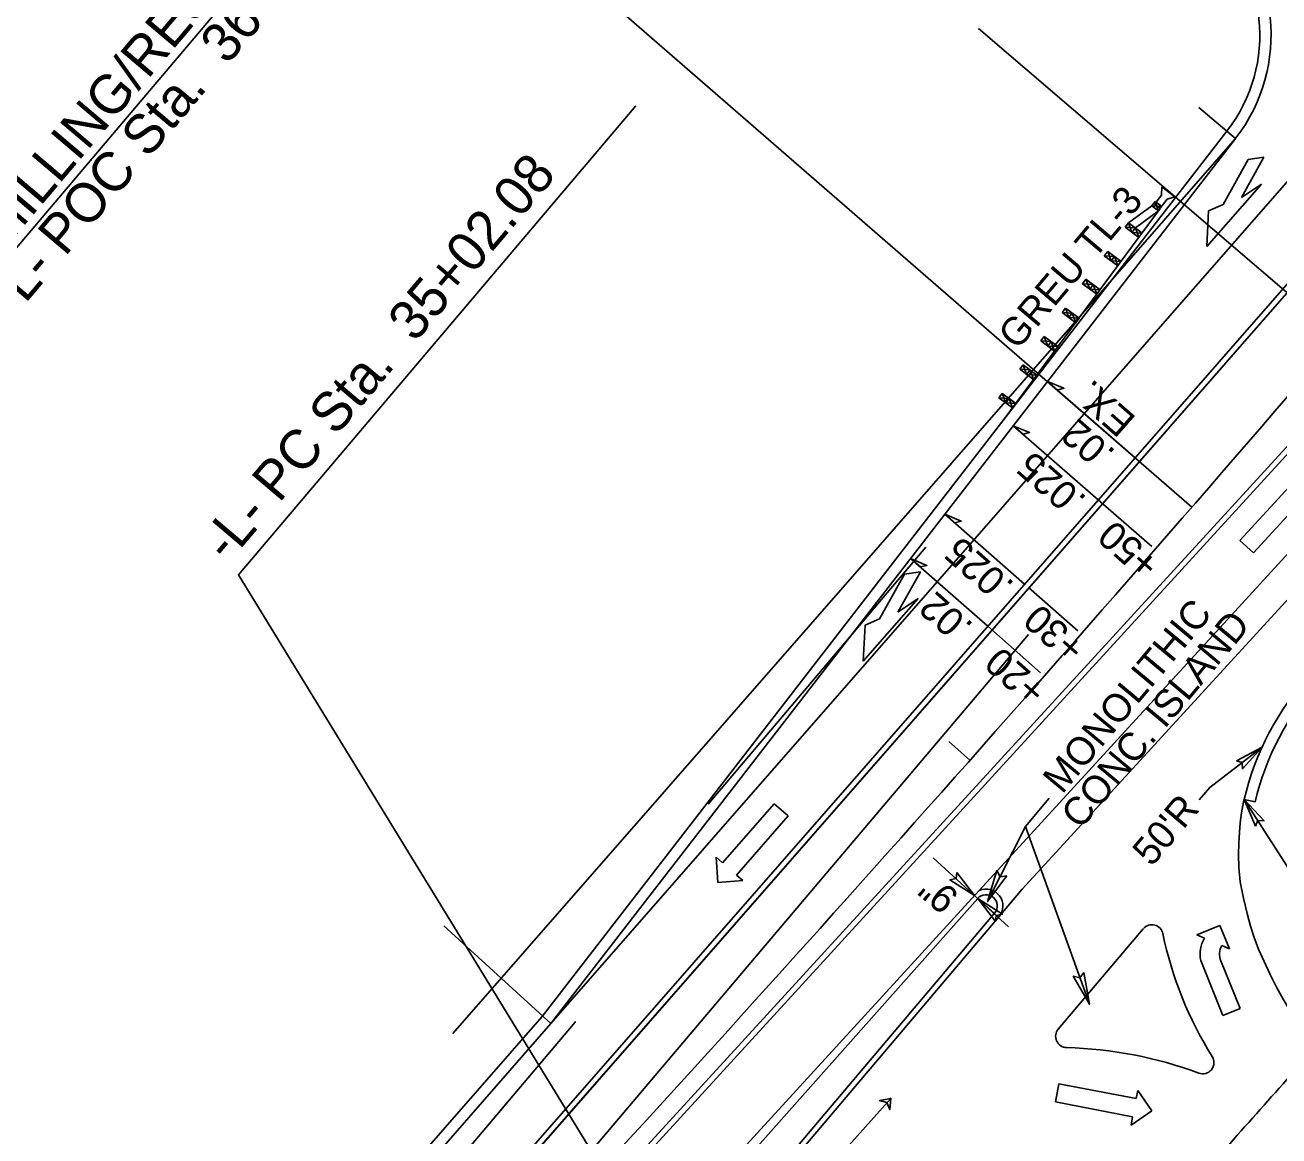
# Model space of a CAD drawing. Extents: x 1761082 to 1764358, y 421907 to 425434.
# Drawn here: x 1762805.2 to 1763028.7, y 423828.1 to 424026 of the extents above; entities that cross this region are included whole.
import ezdxf

# ---------------------------------------------------------------- set-up
doc = ezdxf.new("R2010")
doc.units = 0
for name, color, linetype in [('MARK DUAL LEFT TURN ARROWS CELL', 7, 'Continuous'), ('MARK HOOKS CENTER STRAIGHT LEFT TURN ARROW CELL', 7, 'Continuous'), ('MARK LEFT TURN ARROW CELL', 7, 'Continuous'), ('MARK STRAIGHT RIGHT ARROW CELL', 7, 'Continuous'), ('MARK UTURN ARROW CELL', 7, 'Continuous'), ('Prop Mkg 3ft Min Skp 3ft Wide White', 7, 'Continuous'), ('Prop Mkg 3ft Min Skp 9ft Wide White', 7, 'Continuous'), ('Prop Mkg Min Skp 6ft Yellow', 7, 'Continuous'), ('Prop Mkg Skp Wht', 7, 'Continuous'), ('Prop Mkg Solid White Diagonals', 7, 'Continuous'), ('Prop Mkg Solid White Edge Line', 7, 'Continuous'), ('Prop Mkg Solid White Lane Line', 7, 'Continuous'), ('Prop Mkg Solid White Multiple Diagonals V8i', 7, 'Continuous'), ('Prop Mkg Solid Yel Skip LT', 7, 'Continuous'), ('Prop Mkg Solid Yel Skip RT', 7, 'Continuous'), ('Prop Mkg Solid Yellow Diagonals', 7, 'Continuous'), ('Prop Mkg Solid Yellow Edge Line', 7, 'Continuous'), ('Prop Mkg Solid Yellow Lane Line', 7, 'Continuous'), ('Prop Mkg Yld Lin', 7, 'Continuous'), ('Scratch_Level_0', 7, 'Continuous'), ('Scratch_Level_1', 7, 'Continuous'), ('Scratch_Level_5', 7, 'Continuous')]:
    doc.layers.add(name, color=color, linetype=linetype)

msp = doc.modelspace()

# ---------------------------------------------------------------- linework, layer by layer
at = {"layer": 'MARK DUAL LEFT TURN ARROWS CELL'}
msp.add_line((1762975.13, 424025.41), (1763039.28, 423970.45), dxfattribs=at)
at = {"layer": 'MARK HOOKS CENTER STRAIGHT LEFT TURN ARROW CELL'}
msp.add_line((1762973.59, 423895.06), (1762969.85, 423898.37), dxfattribs=at)
at = {"layer": 'MARK LEFT TURN ARROW CELL'}
for p, q in [((1762897.35, 423849.4), (1763019.39, 424007.14)), ((1763024.42, 423887.61), (1763022.48, 423888.07)), ((1762783.77, 423719.57), (1762897.35, 423849.4))]:
    msp.add_line(p, q, dxfattribs=at)
for centre, radius, start, end in [((1762997.25, 424024.27), 28, 322.2701, 49.4412), ((1763071.14, 423876.61), 48, 137.5234, 166.7543)]:
    msp.add_arc(centre, radius, start, end, dxfattribs=at)
at = {"layer": 'MARK STRAIGHT RIGHT ARROW CELL'}
for p, q in [((1763014.4, 424011.37), (1763020.91, 424005.82)), ((1762881.42, 423846.38), (1763020.91, 424005.82)), ((1762879.8, 423865.54), (1762898.9, 423848.13))]:
    msp.add_line(p, q, dxfattribs=at)
msp.add_arc((1758482.74, 427874.03), 6000, 317.523415, 319.730103, dxfattribs=at)
at = {"layer": 'MARK UTURN ARROW CELL'}
for points in [[(1763013.15, 423940.16), (1762869.88, 424064.58), (1762781.79, 423960.6)], [(1762907.27, 423823.58), (1762843.21, 423928.07), (1762914.03, 424011.67)]]:
    msp.add_lwpolyline(points, dxfattribs=at)
at = {"layer": 'Prop Mkg 3ft Min Skp 3ft Wide White'}
msp.add_arc((1758482.74, 427874.03), 6000, 317.523415, 319.730103, dxfattribs=at)
at = {"layer": 'Prop Mkg 3ft Min Skp 9ft Wide White'}
for p, q in [((1762979.66, 423955.77), (1762897.35, 423849.4)), ((1762897.35, 423849.4), (1762821.72, 423762.95))]:
    msp.add_line(p, q, dxfattribs=at)
at = {"layer": 'Prop Mkg Skp Wht'}
for p, q in [((1762898.9, 423848.13), (1763020.98, 424005.91)), ((1762785.28, 423718.25), (1762898.9, 423848.13))]:
    msp.add_line(p, q, dxfattribs=at)
msp.add_lwpolyline([(1763022.48, 423888.07), (1763022.37, 423887.64), (1763022.01, 423885.7), (1763021.78, 423883.92), (1763021.64, 423882.16), (1763021.52, 423880.28), (1763021.46, 423878.23), (1763021.51, 423875.93), (1763021.77, 423873.37), (1763022.32, 423870.5), (1763022.98, 423867.75), (1763023.58, 423865.5), (1763024.23, 423863.47), (1763025.04, 423861.39), (1763026, 423859.2), (1763027.08, 423856.89), (1763028.24, 423854.59), (1763029.39, 423852.48), (1763030.53, 423850.55), (1763031.6, 423848.83), (1763032.64, 423847.34), (1763033.63, 423846.15), (1763034.61, 423845.13), (1763035.49, 423844.29)], dxfattribs=at)
for centre, radius, start, end in [((1762997.25, 424024.27), 30, 322.2701, 49.4412), ((1763071.14, 423876.61), 50, 137.5234, 166.7543), ((1758482.74, 427874.03), 6080, 318.179172, 318.487231)]:
    msp.add_arc(centre, radius, start, end, dxfattribs=at)
at = {"layer": 'Prop Mkg Solid White Diagonals'}
for p, q in [((1763090.51, 424047.41), (1762859.56, 423783.42)), ((1762783.48, 423681.64), (1763081.76, 424007.42)), ((1762974.97, 423870.42), (1762920.01, 423808.54)), ((1762941.52, 423824.75), (1762977.99, 423867.8)), ((1763004.49, 423865.04), (1762989.33, 423847.15))]:
    msp.add_line(p, q, dxfattribs=at)
for centre, radius, start, end in [((1762976.46, 423869.09), 2, 319.7301, 138.3886), ((1763006.02, 423863.75), 2, 11.5856, 139.7301), ((1763072.63, 423877.41), 66, 191.5856, 212.1906), ((1762990.86, 423845.86), 2, 139.7301, 268.5347), ((1762988.94, 423770.88), 73, 69.6011, 88.5347), ((1763015.08, 423841.18), 2, 249.6011, 32.1906)]:
    msp.add_arc(centre, radius, start, end, dxfattribs=at)
at = {"layer": 'Prop Mkg Solid White Edge Line'}
for p, q in [((1762926.94, 423887.21), (1762965.72, 423932.99)), ((1762864.1, 423775.9), (1762984.04, 423917.48))]:
    msp.add_line(p, q, dxfattribs=at)
at = {"layer": 'Prop Mkg Solid White Lane Line'}
for p, q in [((1762859.56, 423783.42), (1763090.51, 424047.41)), ((1762783.48, 423681.64), (1763081.76, 424007.42)), ((1762920.01, 423808.54), (1762974.97, 423870.42)), ((1762941.52, 423824.75), (1762977.99, 423867.8)), ((1762989.33, 423847.15), (1763004.49, 423865.04))]:
    msp.add_line(p, q, dxfattribs=at)
for centre, radius, start, end in [((1762976.46, 423869.09), 2, 319.7301, 138.3886), ((1763006.02, 423863.75), 2, 11.5856, 139.7301), ((1763072.63, 423877.41), 66, 191.5856, 212.1906), ((1762990.86, 423845.86), 2, 139.7301, 268.5347), ((1762988.94, 423770.88), 73, 69.6011, 88.5347), ((1763015.08, 423841.18), 2, 249.6011, 32.1906)]:
    msp.add_arc(centre, radius, start, end, dxfattribs=at)
at = {"layer": 'Prop Mkg Solid White Multiple Diagonals V8i'}
for p, q in [((1762988.96, 423878.66), (1763083.82, 423982.27)), ((1762982.91, 423872.06), (1762988.96, 423878.66)), ((1762977.97, 423867.77), (1762974.98, 423870.43)), ((1762978.75, 423867.15), (1762982.91, 423872.06))]:
    msp.add_line(p, q, dxfattribs=at)
at = {"layer": 'Prop Mkg Solid Yel Skip RT'}
for p, q in [((1762996.47, 423941.44), (1763005.98, 423933.15)), ((1762984.02, 423925.81), (1762992.82, 423918.1)), ((1762976.76, 423918.91), (1762986.15, 423910.64)), ((1762983.49, 423883.27), (1762976.74, 423869.86)), ((1762980.47, 423865.38), (1762967.03, 423877.68))]:
    msp.add_line(p, q, dxfattribs=at)
for points in [[(1763025.65, 423897.37), (1763016.34, 423890.21), (1763014.46, 423887.98)], [(1762994.89, 423851.58), (1762983.49, 423883.27), (1762987.74, 423888.29)], [(1763022.48, 423888.07), (1763032.31, 423872.76), (1763035.15, 423876.11)]]:
    msp.add_lwpolyline(points, dxfattribs=at)
at = {"layer": 'Prop Mkg Solid Yellow Diagonals'}
for p, q in [((1763018.72, 423994.09), (1763023.17, 424002.06)), ((1763025.97, 424002.47), (1763021.97, 423995.3)), ((1763023.17, 424002.06), (1763025.97, 424002.47)), ((1763025.56, 423997.71), (1763015.79, 423986.55)), ((1763021.97, 423995.3), (1763025.56, 423997.71)), ((1763016.12, 423992.95), (1763018.72, 423994.09)), ((1763015.79, 423986.55), (1763016.12, 423992.95)), ((1763021.7, 423934.21), (1763031.17, 423944.51)), ((1763033.6, 423942.28), (1763024.13, 423931.98)), ((1763024.13, 423931.98), (1763021.7, 423934.21)), ((1762957.5, 423920.24), (1762961.95, 423928.21)), ((1762964.76, 423928.62), (1762960.75, 423921.44)), ((1762961.95, 423928.21), (1762964.76, 423928.62)), ((1762964.35, 423923.86), (1762954.58, 423912.7)), ((1762960.75, 423921.44), (1762964.35, 423923.86)), ((1762954.91, 423919.1), (1762957.5, 423920.24)), ((1762954.58, 423912.7), (1762954.91, 423919.1)), ((1762929.48, 423876.76), (1762938.69, 423887.3)), ((1762938.69, 423887.3), (1762941.18, 423885.13)), ((1762941.18, 423885.13), (1762931.96, 423874.59)), ((1762928.68, 423873.27), (1762928.35, 423877.75)), ((1762928.35, 423877.75), (1762929.48, 423876.76)), ((1762931.96, 423874.59), (1762933.09, 423873.6)), ((1762933.09, 423873.6), (1762928.68, 423873.27)), ((1763014.05, 423863.93), (1763018.12, 423865.61)), ((1763018.12, 423865.61), (1763019.83, 423861.45)), ((1763015.41, 423863.34), (1763014.05, 423863.93)), ((1763019.83, 423861.45), (1763018.47, 423862.03)), ((1763018.67, 423849.56), (1763014.75, 423859.36)), ((1763018.33, 423859.28), (1763021.73, 423850.79)), ((1763021.73, 423850.79), (1763018.67, 423849.56)), ((1762988.84, 423834.17), (1762989.46, 423837.41)), ((1762989.46, 423837.41), (1763003.21, 423834.76)), ((1763003.21, 423834.76), (1763003.5, 423836.23)), ((1763003.5, 423836.23), (1763006, 423832.59)), ((1763002.59, 423831.52), (1762988.84, 423834.17)), ((1763006, 423832.59), (1763002.3, 423830.05)), ((1763002.3, 423830.05), (1763002.59, 423831.52))]:
    msp.add_line(p, q, dxfattribs=at)
for centre, radius, start, end in [((1763019.85, 423860.55), 5.25, 147.8228, 193.1345), ((1763021.35, 423860.5), 3.27, 152.1524, 201.8105)]:
    msp.add_arc(centre, radius, start, end, dxfattribs=at)
at = {"layer": 'Prop Mkg Solid Yellow Edge Line'}
for p, q in [((1762898.9, 423848.13), (1763091.01, 424067.73)), ((1762975.24, 423871.83), (1763081.55, 423987.94))]:
    msp.add_line(p, q, dxfattribs=at)
at = {"layer": 'Prop Mkg Solid Yellow Lane Line'}
for points in [[(1763021.07, 423894.95), (1763025.65, 423897.37), (1763022.14, 423893.52), (1763022.1, 423894.64)], [(1763024.49, 423883.3), (1763022.48, 423888.07), (1763026.01, 423884.24), (1763024.9, 423884.3)], [(1762971.24, 423875.02), (1762974.41, 423870.92), (1762970.02, 423873.72), (1762971.11, 423873.95)], [(1762980.16, 423874.48), (1762976.74, 423869.86), (1762978.4, 423875.4), (1762978.98, 423874.3)], [(1762978.14, 423866.32), (1762974.97, 423870.42), (1762979.37, 423867.62), (1762978.27, 423867.39)], [(1762993.89, 423857.24), (1762994.89, 423851.58), (1762992.01, 423856.6), (1762993.2, 423856.26)]]:
    msp.add_lwpolyline(points, close=True, dxfattribs=at)
at = {"layer": 'Prop Mkg Yld Lin'}
for p, q in [((1763007.76, 423995.75), (1763006.51, 423994.13)), ((1763007.8, 423997.21), (1763007.76, 423995.75)), ((1763010.13, 423995.41), (1763007.8, 423997.21)), ((1763008.73, 423995.01), (1763010.13, 423995.41)), ((1762979.66, 423955.77), (1763007.52, 423993.32)), ((1763001.84, 423990.8), (1763006.02, 423993.81)), ((1763006.02, 423993.81), (1763006.61, 423994.61)), ((1763006.02, 423993.81), (1763006.31, 423994.21)), ((1763007.22, 423992.91), (1763006.02, 423993.81)), ((1763007.82, 423993.72), (1763006.02, 423993.81)), ((1763006.51, 423994.13), (1763006.99, 423993.76)), ((1763007.82, 423993.72), (1763006.61, 423994.61)), ((1763006.61, 423994.61), (1763007.22, 423992.91)), ((1763006.99, 423993.76), (1763007.48, 423993.39)), ((1763007.48, 423993.39), (1763008.73, 423995.01)), ((1763001.24, 423990), (1763001.84, 423990.8)), ((1763004.3, 423988.98), (1763001.84, 423990.8)), ((1763001.84, 423990.8), (1763002.47, 423989.09)), ((1763003.07, 423989.89), (1763007.22, 423992.91)), ((1763003.7, 423988.18), (1763001.24, 423990)), ((1763003.07, 423989.89), (1763001.24, 423990)), ((1763002.47, 423989.09), (1763003.07, 423989.89)), ((1763002.47, 423989.09), (1763004.3, 423988.98)), ((1763003.7, 423988.18), (1763003.07, 423989.89)), ((1762997.54, 423984.9), (1762998.14, 423985.71)), ((1762999.95, 423983.12), (1762997.54, 423984.9)), ((1762999.34, 423984.81), (1762997.54, 423984.9)), ((1763000.54, 423983.92), (1762998.14, 423985.71)), ((1762998.14, 423985.71), (1762998.74, 423984.01)), ((1762998.74, 423984.01), (1762999.34, 423984.81)), ((1762999.95, 423983.12), (1762999.34, 423984.81)), ((1762998.74, 423984.01), (1763000.54, 423983.92)), ((1762993.67, 423979.93), (1762994.27, 423980.73)), ((1762996.19, 423978.06), (1762993.67, 423979.93)), ((1762995.53, 423979.79), (1762993.67, 423979.93)), ((1762996.79, 423978.86), (1762994.27, 423980.73)), ((1762994.27, 423980.73), (1762994.93, 423978.99)), ((1762994.93, 423978.99), (1762995.53, 423979.79)), ((1762996.19, 423978.06), (1762995.53, 423979.79)), ((1762994.93, 423978.99), (1762996.79, 423978.86)), ((1762990, 423974.8), (1762990.6, 423975.61)), ((1762993.03, 423973.8), (1762990.6, 423975.61)), ((1762990.6, 423975.61), (1762991.22, 423973.9)), ((1762992.44, 423973), (1762990, 423974.8)), ((1762991.81, 423974.7), (1762990, 423974.8)), ((1762991.22, 423973.9), (1762991.81, 423974.7)), ((1762991.22, 423973.9), (1762993.03, 423973.8)), ((1762992.44, 423973), (1762991.81, 423974.7)), ((1762992.44, 423973), (1762993.03, 423973.8)), ((1762986.23, 423969.75), (1762986.83, 423970.56)), ((1762988.68, 423967.94), (1762986.23, 423969.75)), ((1762988.05, 423969.65), (1762986.23, 423969.75)), ((1762989.28, 423968.74), (1762986.83, 423970.56)), ((1762986.83, 423970.56), (1762987.46, 423968.84)), ((1762987.46, 423968.84), (1762988.05, 423969.65)), ((1762987.46, 423968.84), (1762989.28, 423968.74)), ((1762988.68, 423967.94), (1762988.05, 423969.65)), ((1762982.48, 423964.7), (1762983.07, 423965.5)), ((1762984.93, 423962.88), (1762982.48, 423964.7)), ((1762984.3, 423964.59), (1762982.48, 423964.7)), ((1762985.52, 423963.68), (1762983.07, 423965.5)), ((1762983.07, 423965.5), (1762983.7, 423963.79)), ((1762983.7, 423963.79), (1762984.3, 423964.59)), ((1762984.93, 423962.88), (1762984.3, 423964.59)), ((1762983.7, 423963.79), (1762985.52, 423963.68)), ((1762978.76, 423959.6), (1762979.36, 423960.41)), ((1762981.17, 423957.82), (1762978.76, 423959.6)), ((1762980.56, 423959.51), (1762978.76, 423959.6)), ((1762981.77, 423958.62), (1762979.36, 423960.41)), ((1762979.36, 423960.41), (1762979.97, 423958.71)), ((1762979.97, 423958.71), (1762980.56, 423959.51)), ((1762981.77, 423958.62), (1762980.56, 423959.51)), ((1762980.56, 423959.51), (1762981.17, 423957.82)), ((1762979.97, 423958.71), (1762981.77, 423958.62)), ((1762981.17, 423957.82), (1762981.77, 423958.62))]:
    msp.add_line(p, q, dxfattribs=at)
at = {"layer": 'Scratch_Level_0'}
for p, q in [((1762858.8, 423784.07), (1763100.11, 424059.9)), ((1762790.28, 423687.58), (1763082.58, 424006.83)), ((1762824.22, 423706.88), (1762975.24, 423871.83)), ((1762825.16, 423685.85), (1762978.75, 423867.15))]:
    msp.add_line(p, q, dxfattribs=at)
msp.add_arc((1762976.46, 423869.09), 3, 319.7301, 113.9669, dxfattribs=at)
at = {"layer": 'Scratch_Level_1'}
for p, q in [((1762785.64, 423709.58), (1762903.23, 423848.39)), ((1762823.74, 423682.91), (1762959.47, 423834.79))]:
    msp.add_line(p, q, dxfattribs=at)
msp.add_lwpolyline([(1762959.47, 423834.79), (1762957.5, 423834.42), (1762958.8, 423834.05), (1762959.32, 423832.8)], close=True, dxfattribs=at)
msp.add_lwpolyline([(1762959.47, 423834.79), (1762957.5, 423834.42), (1762958.8, 423834.05), (1762959.32, 423832.8)], close=True, dxfattribs=at)
for centre in [(1762903.23, 423848.39), (1762959.47, 423834.79), (1762959.47, 423834.79)]:
    msp.add_circle(centre, 0.0417, dxfattribs=at)
at = {"layer": 'Scratch_Level_5'}
for p, q in [((1762987.4, 423962.52), (1763003.04, 423948.95)), ((1762981.31, 423954.64), (1762996.47, 423941.44)), ((1762969.12, 423938.89), (1762983.33, 423926.42)), ((1762963.02, 423931), (1762976.76, 423918.91))]:
    msp.add_line(p, q, dxfattribs=at)
for points in [[(1762987.4, 423962.52), (1762990.33, 423961.31), (1762989.15, 423961.01)], [(1762981.31, 423954.64), (1762984.23, 423953.43), (1762983.05, 423953.13)], [(1762969.12, 423938.89), (1762972.03, 423937.66), (1762970.86, 423937.36)], [(1762963.02, 423931), (1762965.93, 423929.77), (1762964.75, 423929.48)]]:
    msp.add_lwpolyline(points, close=True, dxfattribs=at)

# ---------------------------------------------------------------- texts
at = {"layer": 'MARK UTURN ARROW CELL'}
for s, p in [('BEGIN MILLING/RESURFACING', (1762780.64, 423961.47)), ('-L- POC Sta.  36+60.00', (1762803.22, 423973.93)), ('-L- PC Sta.  35+02.08', (1762841.39, 423930.03))]:
    msp.add_text(s, height=7, rotation=49.7301, dxfattribs=at).set_placement(p)
at = {"layer": 'Prop Mkg Min Skp 6ft Yellow'}
for s, rotation, p in [('EX.', 138.8292, (1763003.42, 423956.03)), ('.02', 138.8292, (1762999.74, 423950.08)), ('.025', 138.7337, (1762994.6, 423941.78)), ('.025', 138.5428, (1762981.71, 423926.54)), ('.02', 138.4473, (1762974.41, 423919.21))]:
    msp.add_text(s, height=5, rotation=rotation, dxfattribs=at).set_placement(p)
at = {"layer": 'Prop Mkg Solid Yel Skip LT'}
for s, rotation, p in [('MONOLITHIC', 50.1302, (1762990.03, 423888.85)), ('CONC. ISLAND', 50.1302, (1762993.29, 423882.54)), ("50'R", 49.7301, (1763005.97, 423875.92)), ('9"', 139.7301, (1762971.92, 423871.15))]:
    msp.add_text(s, height=5, rotation=rotation, dxfattribs=at).set_placement(p)
at = {"layer": 'Prop Mkg Solid Yel Skip RT'}
for s, p in [('+50', (1763007.79, 423930.57)), ('+30', (1762994.54, 423915.65)), ('+20', (1762987.63, 423908.01))]:
    msp.add_text(s, height=5, rotation=138.5428, dxfattribs=at).set_placement(p)
at = {"layer": 'Prop Mkg Yld Lin'}
msp.add_text('GREU TL-3', height=5, rotation=49.7301, dxfattribs=at).set_placement((1762982.07, 423967.97))

doc.saveas('drawing.dxf')
